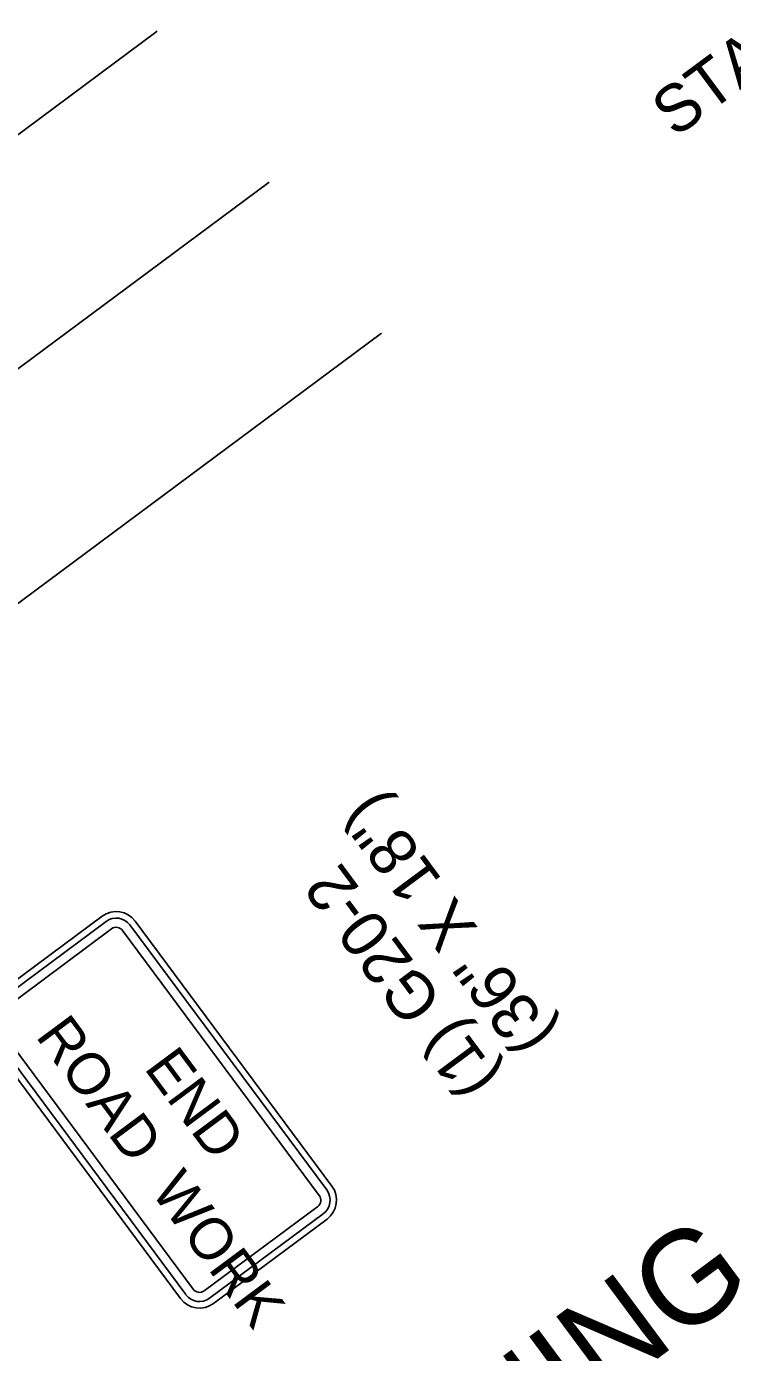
# Model space of a CAD drawing. Extents: x -238 to 1487, y -1123 to 446.
# Drawn here: x -6.3 to 83.5, y -592.5 to -423.8 of the extents above; entities that cross this region are included whole.
import ezdxf

# ---------------------------------------------------------------- set-up
doc = ezdxf.new("R2010")
doc.units = 0
for name, color, linetype in [('P_TC_Signs_Temporary', 7, 'Continuous'), ('R_Border Prem', 7, 'Continuous'), ('R_Draft', 7, 'Continuous')]:
    doc.layers.add(name, color=color, linetype=linetype)

msp = doc.modelspace()

# ---------------------------------------------------------------- linework, layer by layer
at = {"layer": 'P_TC_Signs_Temporary'}
for p, q in [((3.31, -536.98), (-11.14, -547.71)), ((3.81, -537.65), (-10.64, -548.38)), ((31.88, -571.81), (6.84, -538.09)), ((32.55, -571.32), (7.51, -537.6)), ((4.51, -538.58), (-9.95, -549.31)), ((30.94, -572.51), (5.91, -538.79)), ((-11.09, -551.41), (13.95, -585.13)), ((-10.15, -550.71), (14.89, -584.43)), ((-11.76, -551.91), (13.28, -585.63)), ((16.29, -584.64), (30.74, -573.91)), ((16.98, -585.58), (31.43, -574.85)), ((17.48, -586.25), (31.93, -575.51))]:
    msp.add_line(p, q, dxfattribs=at)
for centre, radius, start, end in [((5.1, -539.39), 3, 36.5953, 126.5953), ((5.1, -539.39), 2.17, 36.5953, 126.5953), ((5.1, -539.39), 1, 36.5953, 126.5953), ((30.14, -573.11), 2.17, 306.5953, 36.5953), ((30.14, -573.11), 3, 306.5953, 36.5953), ((30.14, -573.11), 1, 306.5953, 36.5953), ((15.69, -583.84), 2.17, 216.5953, 306.5953), ((15.69, -583.84), 1, 216.5953, 306.5953), ((15.69, -583.84), 3, 216.5953, 306.5953)]:
    msp.add_arc(centre, radius, start, end, dxfattribs=at)
at = {"layer": 'R_Draft'}
for p, q in [((10.3, -424.38), (-128.22, -527.23)), ((24.57, -443.59), (-113.95, -546.45)), ((38.85, -462.81), (-99.68, -565.67))]:
    msp.add_line(p, q, dxfattribs=at)

# ---------------------------------------------------------------- texts
at = {"layer": 'P_TC_Signs_Temporary'}
for s, p in [('ROAD  WORK', (-5.27, -552.25)), ('END', (8.54, -556.31))]:
    msp.add_text(s, height=5.333, rotation=306.5953, dxfattribs=at).set_placement(p)
at = {"layer": 'R_Border Prem'}
for s, height, rotation, p in [('STAGE 3:', 6, 36.6341, (76.22, -438.04)), ('(36" X 18")', 6, 126.5953, (61.15, -551.9)), ('(1) G20-2', 6, 126.5953, (54, -557.48)), ('ADVANCE WARNING', 12, 36.5953, (-41.6, -679.12))]:
    msp.add_text(s, height=height, rotation=rotation, dxfattribs=at).set_placement(p)

doc.saveas('drawing.dxf')
